// Mitsubishi GX Works2 project: MC-42MR-8MTS-F700-H3G-B-LAN   PLC: FX3G

PROGRAM MAIN
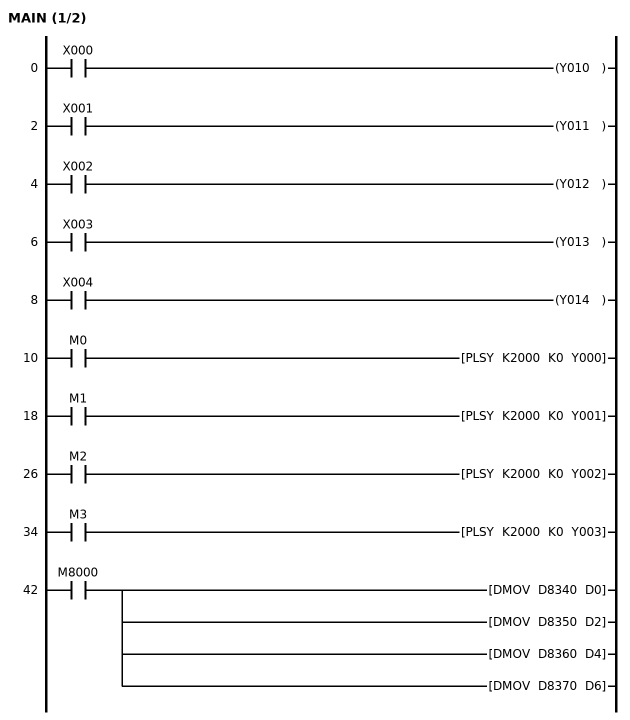
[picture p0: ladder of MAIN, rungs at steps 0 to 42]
0     LD      X000
      OUT     Y010
2     LD      X001
      OUT     Y011
4     LD      X002
      OUT     Y012
6     LD      X003
      OUT     Y013
8     LD      X004
      OUT     Y014
10    LD      M0
      PLSY    K2000 K0 Y000
18    LD      M1
      PLSY    K2000 K0 Y001
26    LD      M2
      PLSY    K2000 K0 Y002
34    LD      M3
      PLSY    K2000 K0 Y003
42    LD      M8000
      DMOV    D8340 D0
      DMOV    D8350 D2
      DMOV    D8360 D4
      DMOV    D8370 D6
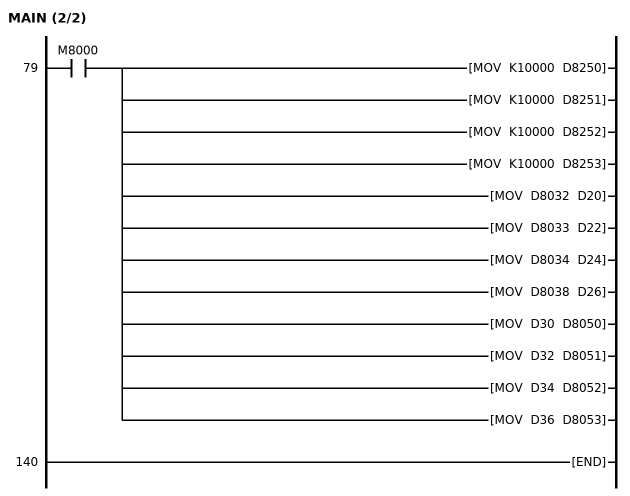
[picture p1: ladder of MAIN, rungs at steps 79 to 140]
79    LD      M8000
      MOV     K10000 D8250
      MOV     K10000 D8251
      MOV     K10000 D8252
      MOV     K10000 D8253
      MOV     D8032 D20
      MOV     D8033 D22
      MOV     D8034 D24
      MOV     D8038 D26
      MOV     D30 D8050
      MOV     D32 D8051
      MOV     D34 D8052
      MOV     D36 D8053
140   END
END_PROGRAM
